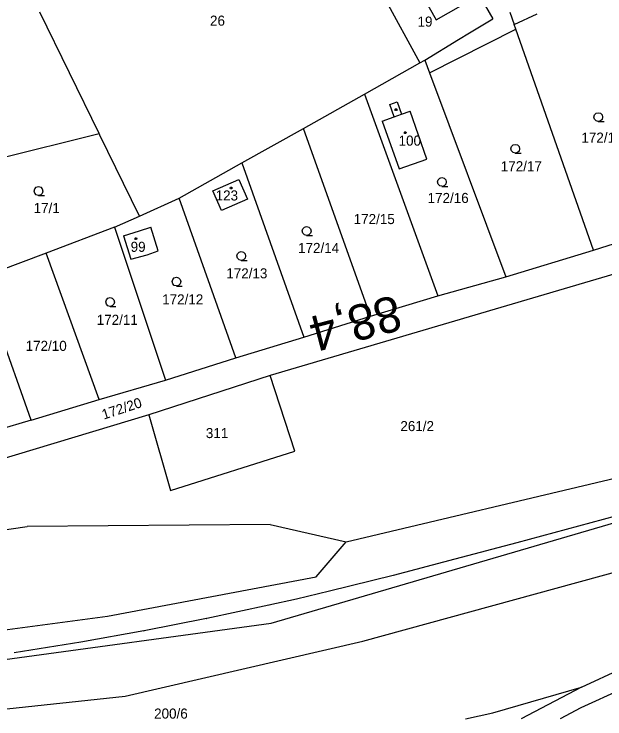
# Model space of a CAD drawing. Extents: x -780000 to -777378, y -1011169 to -1009297.
# Drawn here: x -779086.3 to -778986.4, y -1010479.3 to -1010360.1 of the extents above; entities that cross this region are included whole.
import ezdxf

# ---------------------------------------------------------------- set-up
doc = ezdxf.new("R2010")
doc.units = 0
for name, color, linetype in [('Default', 7, 'Continuous'), ('KN_HRANICE', 7, 'Continuous'), ('KN_KULTURY', 7, 'Continuous'), ('KN_PARCELY', 7, 'Continuous'), ('KN_SLUCKY', 7, 'Continuous'), ('KN_VEDENI', 7, 'Continuous'), ('Vrstva 7', 7, 'Continuous'), ('Železniční svršek', 7, 'Continuous')]:
    doc.layers.add(name, color=color, linetype=linetype)

# ---------------------------------------------------------------- blocks, each defined once
blk = doc.blocks.new('304')
at = {"layer": 'Default'}
blk.add_lwpolyline([(0, 0), (-0.38, 0.1), (-0.65, 0.37), (-0.75, 0.74), (-0.65, 1.11), (-0.38, 1.38), (-0.01, 1.48), (0.36, 1.38), (0.63, 1.11), (0.73, 0.73), (0.63, 0.35), (0.36, 0.08), (-0.02, -0.02), (0.98, -0.02)], dxfattribs=at)
blk = doc.blocks.new('402')
at = {"layer": 'Default'}
blk.add_lwpolyline([(0.09, 0.15), (0.18, 0), (0.09, -0.15), (-0.09, -0.15), (-0.18, 0), (-0.09, 0.15), (0.09, 0.15)], dxfattribs=at)

msp = doc.modelspace()

# ---------------------------------------------------------------- linework, layer by layer
at = {"layer": 'KN_HRANICE'}
for p, q in [((-779023.89, -1010357.02), (-779017.69, -1010368.36)), ((-779071.95, -1010380.31), (-779081.96, -1010359.81)), ((-779002.49, -1010359.8), (-779001.76, -1010361.88)), ((-779001.76, -1010361.88), (-778997.87, -1010360.08)), ((-779016.08, -1010370.08), (-779001.48, -1010362.68)), ((-779001.48, -1010362.68), (-779001.76, -1010361.88)), ((-778988.37, -1010400.03), (-779001.48, -1010362.68)), ((-779027.09, -1010373.66), (-779017.69, -1010368.36)), ((-779017.69, -1010368.36), (-779016.89, -1010367.91)), ((-779016.89, -1010367.91), (-779016.08, -1010370.08)), ((-779016.08, -1010370.08), (-779003.14, -1010404.53)), ((-779037.39, -1010379.46), (-779027.09, -1010373.66)), ((-779027.09, -1010373.66), (-779014.66, -1010407.79)), ((-779022.8, -1010375.42), (-779021.54, -1010374.98)), ((-779022.06, -1010377.52), (-779022.8, -1010375.42)), ((-779021.54, -1010374.98), (-779020.82, -1010377.08)), ((-779020.82, -1010377.08), (-779019.35, -1010376.56)), ((-779016.52, -1010384.66), (-779019.35, -1010376.56)), ((-779024.08, -1010378.22), (-779022.06, -1010377.52)), ((-779024.08, -1010378.22), (-779021.2, -1010386.31)), ((-779047.78, -1010385.31), (-779037.39, -1010379.46)), ((-779026.05, -1010411.22), (-779037.39, -1010379.46)), ((-779098.22, -1010386.86), (-779071.95, -1010380.31)), ((-779071.81, -1010380.59), (-779071.95, -1010380.31)), ((-779065.12, -1010394.29), (-779071.81, -1010380.59)), ((-779058.38, -1010391.28), (-779047.78, -1010385.31)), ((-779047.78, -1010385.31), (-779037.35, -1010414.74)), ((-779021.2, -1010386.31), (-779016.52, -1010384.66)), ((-779052.71, -1010390), (-779048.3, -1010388.08)), ((-779048.3, -1010388.08), (-779046.83, -1010391.44)), ((-779051.24, -1010393.33), (-779052.71, -1010390)), ((-779065.12, -1010394.29), (-779058.38, -1010391.28)), ((-779048.8, -1010418.22), (-779058.38, -1010391.28)), ((-779046.83, -1010391.44), (-779051.24, -1010393.33)), ((-779069.32, -1010396.17), (-779065.12, -1010394.29)), ((-779069.32, -1010396.17), (-779080.88, -1010400.54)), ((-779069.32, -1010396.17), (-779060.72, -1010422.04)), ((-779065.12, -1010396.78), (-779063.17, -1010396.18)), ((-779061.97, -1010400.17), (-779063.17, -1010396.18)), ((-778958.54, -1010396.31), (-779043.02, -1010421.24)), ((-778988.37, -1010400.03), (-778974.46, -1010395.73)), ((-779067.84, -1010397.62), (-779065.12, -1010396.78)), ((-779067.84, -1010397.62), (-779066.59, -1010401.56)), ((-779080.88, -1010400.54), (-779090.81, -1010404.3)), ((-779071.93, -1010425.3), (-779080.88, -1010400.54)), ((-779066.59, -1010401.56), (-779063.82, -1010400.81)), ((-779063.82, -1010400.81), (-779061.97, -1010400.17)), ((-779003.14, -1010404.53), (-778988.37, -1010400.03)), ((-779083.42, -1010428.77), (-779091.99, -1010404.73)), ((-779014.66, -1010407.79), (-779003.14, -1010404.53)), ((-779026.05, -1010411.22), (-779014.66, -1010407.79)), ((-779037.35, -1010414.74), (-779026.05, -1010411.22)), ((-779048.8, -1010418.22), (-779037.35, -1010414.74)), ((-779060.72, -1010422.04), (-779048.8, -1010418.22)), ((-779043.02, -1010421.24), (-779063.54, -1010427.85)), ((-779038.86, -1010434.01), (-779043.02, -1010421.24)), ((-779071.93, -1010425.3), (-779060.72, -1010422.04)), ((-779083.42, -1010428.77), (-779071.93, -1010425.3)), ((-779063.54, -1010427.85), (-779168.06, -1010459.43)), ((-779063.54, -1010427.85), (-779059.85, -1010440.67)), ((-779083.42, -1010428.77), (-779100.12, -1010433.69)), ((-779059.85, -1010440.67), (-779038.86, -1010434.01)), ((-779030.17, -1010449.35), (-778970.59, -1010435.19)), ((-779027.37, -1010466.13), (-778950.06, -1010444.91)), ((-779168.06, -1010459.43), (-779084.08, -1010446.73)), ((-779043.03, -1010446.43), (-779084.08, -1010446.73)), ((-779043.03, -1010446.43), (-779030.17, -1010449.35)), ((-779035.24, -1010455.28), (-779030.17, -1010449.35)), ((-778990.37, -1010473.89), (-778946.9, -1010453.97)), ((-779070.54, -1010461.9), (-779035.24, -1010455.28)), ((-778945.86, -1010456.94), (-778990.5, -1010477.42)), ((-779127.38, -1010469.51), (-779070.54, -1010461.9)), ((-779067.56, -1010475.45), (-779027.37, -1010466.13)), ((-779005.39, -1010478.26), (-778990.37, -1010473.89)), ((-778990.37, -1010473.89), (-779000.59, -1010479.27)), ((-779103.26, -1010479.27), (-779067.56, -1010475.45)), ((-779009.99, -1010479.27), (-779005.39, -1010478.26)), ((-778990.5, -1010477.42), (-778994, -1010479.27))]:
    msp.add_line(p, q, dxfattribs=at)
at = {"layer": 'KN_SLUCKY'}
for p, q in [((-779018.79, -1010354.32), (-779014.92, -1010361.14)), ((-779014.92, -1010361.14), (-779007.64, -1010356.95)), ((-779007.64, -1010356.95), (-779005.36, -1010360.92)), ((-779009.32, -1010363.32), (-779005.36, -1010360.92)), ((-779011.17, -1010364.44), (-779009.32, -1010363.32)), ((-779016.89, -1010367.91), (-779011.17, -1010364.44)), ((-779022.06, -1010377.52), (-779020.82, -1010377.08))]:
    msp.add_line(p, q, dxfattribs=at)
at = {"layer": 'KN_VEDENI'}
for p, q in [((-779042.85, -1010463.08), (-778940.99, -1010433.26)), ((-779130.44, -1010475.03), (-779042.85, -1010463.08))]:
    msp.add_line(p, q, dxfattribs=at)
at = {"layer": 'Železniční svršek'}
for points in [[(-778980.43, -1010443.86), (-778990.86, -1010446.68)], [(-778990.86, -1010446.68), (-779001.31, -1010449.51)], [(-779001.31, -1010449.51), (-779011.77, -1010452.29)], [(-779011.77, -1010452.29), (-779022.21, -1010455.01)], [(-779022.22, -1010455.01), (-779032.96, -1010457.68)], [(-779032.97, -1010457.68), (-779038.58, -1010459.01)], [(-779038.58, -1010459.01), (-779043.23, -1010460.07)], [(-779043.24, -1010460.07), (-779053.74, -1010462.32)], [(-779053.76, -1010462.32), (-779064.35, -1010464.39)], [(-779064.36, -1010464.39), (-779075.03, -1010466.3)], [(-779075.05, -1010466.31), (-779086.32, -1010468.1)]]:
    msp.add_lwpolyline(points, dxfattribs=at)
for centre, start, end in [((-778990.6, -1010447.65), 105.1366, 105.1456), ((-779001.57, -1010448.55), 284.8902, 285.1456), ((-779012.02, -1010451.33), 284.599, 284.8902), ((-779022.46, -1010454.04), 283.9397, 284.599), ((-779033.2, -1010456.71), 283.2752, 283.9397), ((-779038.81, -1010458.03), 282.9011, 283.2752), ((-779043.45, -1010459.1), 282.0549, 282.9011), ((-779053.95, -1010461.34), 281.0645, 282.0549), ((-779064.54, -1010463.41), 280.149, 281.0645), ((-779075.2, -1010465.32), 279.019, 280.149)]:
    msp.add_arc(centre, 1, start, end, dxfattribs=at)

# ---------------------------------------------------------------- block references
at = {"layer": 'KN_KULTURY'}
for name, p in [('402', (-779021.73, -1010376.29)), ('304', (-778987.53, -1010378.29)), ('402', (-779020.18, -1010380.17)), ('304', (-779001.56, -1010383.64)), ('304', (-779013.97, -1010389.25)), ('304', (-779082.18, -1010390.79)), ('402', (-779049.61, -1010389.53)), ('304', (-779036.84, -1010397.54)), ('402', (-779065.72, -1010398.09)), ('304', (-779047.89, -1010401.77)), ('304', (-779058.85, -1010406.09)), ('304', (-779070.07, -1010409.54))]:
    msp.add_blockref(name, p, dxfattribs=at)

# ---------------------------------------------------------------- texts
at = {"layer": 'KN_PARCELY'}
for s, p in [('26', (-779053.19, -1010362.1)), ('19', (-779018.1, -1010362.26)), ('100', (-779021.3, -1010382.38)), ('172/18', (-778990.39, -1010381.87)), ('172/17', (-779004.02, -1010386.71)), ('123', (-779052.24, -1010391.65)), ('172/16', (-779016.4, -1010392.07)), ('17/1', (-779083.02, -1010393.78)), ('172/15', (-779028.9, -1010395.64)), ('99', (-779066.61, -1010400.33)), ('172/14', (-779038.3, -1010400.52)), ('172/13', (-779050.44, -1010404.81)), ('172/12', (-779061.28, -1010409.21)), ('172/11', (-779072.35, -1010412.67)), ('172/10', (-779084.37, -1010417.07)), ('261/2', (-779021, -1010430.63)), ('311', (-779053.89, -1010431.81)), ('200/6', (-779062.64, -1010479.22))]:
    msp.add_text(s, height=1.7, dxfattribs=at).set_placement(p)
msp.add_text('172/20', height=1.7, rotation=18.277, dxfattribs=at).set_placement((-779071.16, -1010428.7))
at = {"layer": 'Vrstva 7'}
msp.add_text('88,4', height=6, rotation=194.599, dxfattribs=at).set_placement((-779021.78, -1010407.56))

doc.saveas('drawing.dxf')
